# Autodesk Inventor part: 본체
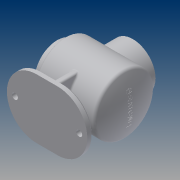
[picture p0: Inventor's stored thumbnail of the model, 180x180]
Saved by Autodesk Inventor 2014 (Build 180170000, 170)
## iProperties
Created: 2016-04
Part Number: 본체
Material: 일반
Document SubType Name: Modeling
Designer: owner
Density: 1 g/cm^3
Appearance: 기본값
Author: owner
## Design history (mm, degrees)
sketch "스케치1"
  geometry: L1 (17.5, 0)-(-17.5, 0); L2 (17.5, 50)-(-17.5, 50); L3 (-17.5, -50)-(17.5, -50); A1 r 50 centre (17.5, 0) between (17.5, -50) and (17.5, 50); A2 r 50 centre (-17.5, 0) between (-17.5, 50) and (-17.5, -50); 2 further points
  constraints: 8 end point, 4 point on circle, 4 tangent, 2 centre point, 1 coincident, 1 horizontal, 1 midpoint, 1 parallel
  dimensions: "d0" = 100 distance between parallel lines of L2 L3; "d1" = 135 dimension on A1 A2
extrude "돌출1" new body sketch "스케치1" distance "d2" = 10; taper "d3" = 0 deg
sketch "스케치2"
  geometry: L1 (-17.5, -50)-(17.5, -50) reference; L2 (17.5, 50)-(-17.5, 50) reference; C1 r 5 at (-54, 0); C2 r 5 at (54, 0); 1 further point
  constraints: 2 centre point
  dimensions: "d4" = 10 diameter of C1; "d5" = 10 diameter of C2; "d6" = 54 distance of C2.centre point (0, 0); "d7" = 54 distance of point (0, 0) C1.centre; "d8" = 50 distance from line of L2 C1.centre; "d9" = 50 distance from line of L1 C2.centre
extrude "돌출2" cut sketch "스케치2" distance "d10" = 10; taper "d11" = 0 deg
sketch "스케치3"
  geometry: L1 (0, -50)-(0, 50) reference; C1 r 50 at (79, 0); 1 further point
  constraints: 1 centre point
  dimensions: "d12" = 79 distance from line of L1 C1.centre; "d14" = 100 diameter of C1; "d15" = 93.49332 distance of C1.centre L1.end
extrude "돌출3" join sketch "스케치3" stored distance "d16" = 100; taper "d17" = 0 deg
sketch "스케치5"
  geometry: L1 (50, 29)-(50, 129) reference; L2 (50, 129)-(50, 79); L3 (50, 79)-(60.913, 79); L4 (17.5, 0)-(-17.5, 0) reference; A1 r 120 centre (-59.087, 79) between (60.913, 79) and (50, 129); 1 further point
  constraints: 4 end point, 2 point on circle, 1 centre point, 1 perpendicular
  dimensions: "d18" = 120 radius of A1; "d19" = 79 distance between parallel lines of L4 L3; "d22" = 10.91288 distance from line of L3.end L1
revolve "회전1" sketch "스케치5" stored, may be unused: angle "d23" = 90 deg
sketch "스케치6"
  geometry: C1 r 50 at (0, 0) reference; C2 r 38 at (0, 0); 1 further point
  constraints: 1 centre point, 1 coincident
  dimensions: "d24" = 76 diameter of C2
extrude "돌출4" join sketch "스케치6" distance "d25" = 12; taper "d26" = 0 deg
hole "구멍1" diameter "d29" = 54; stored, may be unused: countersink angle "d33" = 90 deg, drill point angle "d35" = 0 deg; dims "d27" = 10, "d28" = 10, "d30" = 6, "d31" = 4, "d32" = 2, "d34" = 15
sketch "스케치7"
  geometry: L1 (-50, 129)-(50, 129) reference; L2 (-50, 29)-(50, 29) reference; L3 (48.058, 126)-(48.058, 79); L4 (48.058, 79)-(57.913, 79); A1 r 120 centre (-59.087, 79) between (50, 29) and (50, 129) reference; A2 r 117 centre (-59.087, 79) between (57.913, 79) and (48.058, 126); 1 further point
  constraints: 4 end point, 2 point on circle, 1 centre point, 1 parallel, 1 perpendicular
  dimensions: "d36" = 3 radial gap between concentric circles of A1 A2; "d39" = 50 distance between parallel lines of L1 L4; "d40" = 1.94236 distance from line of A1.end L3
revolve "회전2" sketch "스케치7" stored, may be unused: angle "d41" = 90 deg
hole "구멍2" diameter "d44" = 94; stored, may be unused: countersink angle "d48" = 90 deg, drill point angle "d50" = 0 deg; dims "d42" = 10, "d43" = 10, "d45" = 6, "d46" = 4, "d47" = 2, "d49" = 95.058
sketch "스케치9" dims "d51" = 65
  geometry: C1 r 27 at (0, 0) reference; C2 r 38 at (0, 0) reference; 3 further points
  constraints: 2 vertical alignment, 1 coincident, 2 other
hole "구멍3" sketch "스케치9" at (0, 32.5) diameter "d52" = 3.242; stored, may be unused: countersink angle "d56" = 90 deg, drill point angle "d58" = 118 deg; dims "d53" = 8, "d54" = 4, "d55" = 2, "d57" = 10
node "작업 평면1"
sketch "스케치10"
  geometry: C1 r 38 at (0, 0); 1 further point
  constraints: 1 centre point, 1 coincident
  dimensions: "d63" = 76 diameter of C1
extrude "돌출5" join sketch "스케치10" stored distance "d64" = 12; taper "d65" = 0 deg
sketch "스케치11" dims "d66" = 65
  geometry: C1 r 38 at (0, 0) reference; 2 further points
  constraints: 2 vertical alignment, 1 coincident, 2 other
hole "구멍4" sketch "스케치11" at (0, 32.5) diameter "d67" = 3.242; stored, may be unused: countersink angle "d71" = 90 deg, drill point angle "d73" = 118 deg; dims "d68" = 8, "d69" = 4, "d70" = 2, "d72" = 10
hole "구멍5" diameter "d79" = 54; stored, may be unused: countersink angle "d83" = 90 deg, drill point angle "d85" = 0 deg; dims "d77" = 10, "d78" = 10, "d80" = 8, "d81" = 4, "d82" = 2, "d84" = 44
sketch "스케치12"
  geometry: L1 (-17.5, 10)-(-67.5, 10) reference; L2 (67.5, 10)-(17.5, 10) reference; L3 (-40, 10)-(-36.487, 29.921); L4 (36.487, 29.921)-(40, 10); L5 (-40, 10)-(40, 10); L6 (-36.487, 29.921)-(36.487, 29.921); 1 further point
  constraints: 8 end point, 2 point on line, 1 parallel
  dimensions: "d86" = 40 horizontal distance of point (0, 0) L4.end; "d87" = 40 horizontal distance of L3.start point (0, 0); "d88" = 100 deg angle of L1 L3; "d89" = 100 deg angle of L2 L4; "d90" = 19.92068 distance between parallel lines of L6 L2
extrude "돌출6" join sketch "스케치12" stored distance "d91" = 10; taper "d92" = 0 deg
sketch "스케치13"
  geometry: L1 (10, -50)-(10, 50) reference; L2 (49, 40)-(10, 40); L3 (49, -40)-(10, -40); L4 (10, 40)-(10, -40); A1 r 50 centre (79, 0) between (49, 40) and (49, -40) reference; A2 r 50 centre (79, 0) between (49, 40) and (49, -40); 1 further point
  constraints: 6 end point, 4 point on circle, 3 perpendicular, 2 point on line, 1 centre point, 1 coincident, 1 concentric
  dimensions: "d93" = 40 distance from line of point (0, 0) L3; "d94" = 40 distance from line of L2 point (0, 0)
extrude "돌출7" join sketch "스케치13" stored distance "d95" = 10; taper "d96" = 0 deg
node "작업 평면4"
  node "작업 평면3"
fillet "모깎기2" dims "d103" = 5
fillet "모깎기3" dims "d104" = 2
fillet "모깎기4" dims "d105" = 2
chamfer "모따기1" distance "d106" = 3; stored, may be unused: second distance "d107" = 2, angle "d108" = 45 deg
chamfer "모따기2" distance "d109" = 1; stored, may be unused: second distance "d110" = 2, angle "d111" = 45 deg
fillet "모깎기5" dims "d112" = 3
fillet "모깎기6" dims "d113" = 3
fillet "모깎기7" dims "d114" = 3
fillet "모깎기8" dims "d115" = 3
fillet "모깎기9" dims "d116" = 3
fillet "모깎기10" dims "d117" = 3
fillet "모깎기11" dims "d118" = 3
fillet "모깎기12" dims "d119" = 3
chamfer "모따기3" distance "d120" = 1; stored, may be unused: second distance "d121" = 2, angle "d122" = 45 deg
node "작업 평면5"
sketch "스케치18"
  geometry: L1 (0, -50)-(0, 50) reference; L2 (48.016, 40)-(13, 40) reference; 2 further points
  constraints: 1 other
  dimensions: "d124" = 79 distance from line of L1 point (79, 0); "d125" = 40 distance from line of L2 point (79, 0)
feature "엠보싱1" sketch "스케치18" dims "d126" = 0.5, "d127" = 0
fillet "모깎기13" dims "d128" = 5
node "솔리드1"
pattern_circular "원형 패턴1" dims angle "d60" = 360 deg
pattern_circular "원형 패턴2" dims angle "d75" = 360 deg
other parameters: "d62" = -144, "d99" = 0.5, "d123" = 92.5
